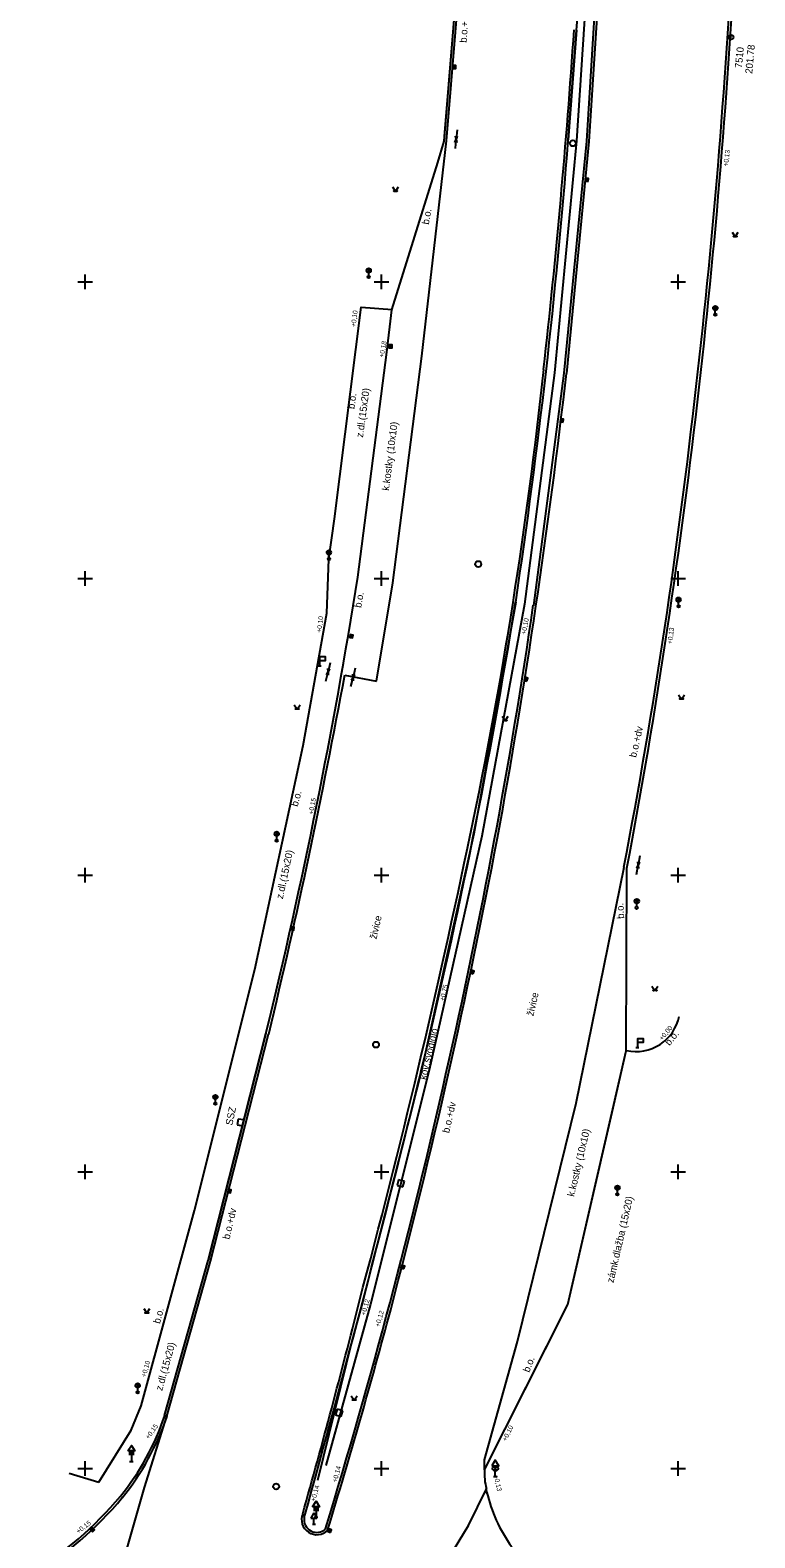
# Model space of a CAD drawing. Extents: x -599151 to -598424, y -1163476 to -1161924.
# Drawn here: x -598704.6 to -598643.5, y -1162630.9 to -1162503.8 of the extents above; entities that cross this region are included whole.
import ezdxf

# ---------------------------------------------------------------- set-up
doc = ezdxf.new("R2010")
doc.units = 0
for name, color, linetype in [('Vrstva 10', 7, 'Continuous'), ('Vrstva 14', 7, 'Continuous'), ('Vrstva 19', 7, 'Continuous'), ('Vrstva 2', 7, 'Continuous'), ('Vrstva 21', 7, 'Continuous'), ('Vrstva 23', 7, 'Continuous'), ('Vrstva 25', 7, 'Continuous'), ('Vrstva 29', 7, 'Continuous'), ('Vrstva 44', 7, 'Continuous'), ('Vrstva 49', 7, 'Continuous'), ('Vrstva 50', 7, 'Continuous'), ('Vrstva 62', 7, 'Continuous'), ('Vrstva 63', 7, 'Continuous'), ('Vrstva 7', 7, 'Continuous')]:
    doc.layers.add(name, color=color, linetype=linetype)

msp = doc.modelspace()

# ---------------------------------------------------------------- linework, layer by layer
at = {"layer": 'Vrstva 10'}
msp.add_lwpolyline([(-598657.82, -1162452.73), (-598658.26, -1162473.18), (-598658.32, -1162480.29), (-598658.04, -1162493.44), (-598657.77, -1162501.13), (-598658.57, -1162513.12), (-598660.43, -1162532.68), (-598662.96, -1162552.16), (-598666.55, -1162571.73), (-598670.98, -1162591.44), (-598675.92, -1162611.16), (-598679.71, -1162624.76)], dxfattribs=at)
at = {"layer": 'Vrstva 14'}
for points in [[(-598674.08, -1162517.01), (-598673.83, -1162517.38), (-598673.58, -1162517.01)], [(-598645.44, -1162520.83), (-598645.19, -1162521.2), (-598644.94, -1162520.83)], [(-598649.96, -1162559.8), (-598649.71, -1162560.18), (-598649.46, -1162559.8)], [(-598682.36, -1162560.65), (-598682.11, -1162561.02), (-598681.86, -1162560.65)], [(-598664.84, -1162561.62), (-598664.59, -1162561.99), (-598664.34, -1162561.62)], [(-598652.2, -1162584.37), (-598651.95, -1162584.74), (-598651.7, -1162584.37)], [(-598695.04, -1162611.54), (-598694.79, -1162611.92), (-598694.54, -1162611.54)], [(-598677.56, -1162618.88), (-598677.31, -1162619.25), (-598677.06, -1162618.88)]]:
    msp.add_lwpolyline(points, dxfattribs=at)
for centre in [(-598673.95, -1162517.36), (-598673.7, -1162517.36), (-598645.31, -1162521.18), (-598645.06, -1162521.18), (-598649.84, -1162560.15), (-598649.59, -1162560.15), (-598682.24, -1162561), (-598681.99, -1162561), (-598664.71, -1162561.97), (-598664.46, -1162561.97), (-598652.07, -1162584.72), (-598651.82, -1162584.72), (-598694.92, -1162611.89), (-598694.67, -1162611.89), (-598677.43, -1162619.23), (-598677.18, -1162619.23)]:
    msp.add_circle(centre, 0.025, dxfattribs=at)
at = {"layer": 'Vrstva 19'}
for p, q in [((-598680.35, -1162557.36), (-598680.1, -1162557.36)), ((-598680.23, -1162556.91), (-598680.23, -1162557.36)), ((-598653.55, -1162589.54), (-598653.3, -1162589.54)), ((-598653.42, -1162589.09), (-598653.42, -1162589.54)), ((-598680.71, -1162628.76), (-598680.96, -1162629.19)), ((-598680.71, -1162628.76), (-598680.46, -1162629.19)), ((-598680.96, -1162629.19), (-598680.46, -1162629.19)), ((-598680.83, -1162629.69), (-598680.58, -1162629.69)), ((-598680.71, -1162629.69), (-598680.71, -1162629.19))]:
    msp.add_line(p, q, dxfattribs=at)
for points in [[(-598680.23, -1162556.91), (-598679.73, -1162556.91), (-598679.73, -1162556.61), (-598680.23, -1162556.61)], [(-598653.42, -1162589.09), (-598652.92, -1162589.09), (-598652.92, -1162588.79), (-598653.42, -1162588.79)]]:
    msp.add_lwpolyline(points, close=True, dxfattribs=at)
at = {"layer": 'Vrstva 2'}
for radius in [0.187, 0.00896]:
    msp.add_circle((-598645.52, -1162504.39), radius, dxfattribs=at)
at = {"layer": 'Vrstva 21'}
for points in [[(-598658.56, -1162503.8), (-598659.26, -1162513.05)], [(-598663.69, -1162551.99), (-598667.22, -1162571.53), (-598671.67, -1162591.57), (-598676.61, -1162610.99), (-598677.51, -1162614.29), (-598680.39, -1162626.01)]]:
    msp.add_lwpolyline(points, dxfattribs=at)
for centre, radius, start, end in [((-598705.14, -1162500.39), 46.7, 355.8125, 2.7473), ((-599218.17, -1162469.19), 560.63, 351.5066, 355.5127)]:
    msp.add_arc(centre, radius, start, end, dxfattribs=at)
at = {"layer": 'Vrstva 23'}
for p, q in [((-598687.1, -1162595.56), (-598687.18, -1162596.05)), ((-598686.61, -1162595.64), (-598687.1, -1162595.56)), ((-598686.69, -1162596.13), (-598686.61, -1162595.64)), ((-598687.18, -1162596.05), (-598686.69, -1162596.13)), ((-598673.56, -1162600.67), (-598673.68, -1162601.15)), ((-598673.08, -1162600.79), (-598673.56, -1162600.67)), ((-598673.2, -1162601.27), (-598673.08, -1162600.79)), ((-598673.68, -1162601.15), (-598673.2, -1162601.27)), ((-598678.74, -1162620.01), (-598678.88, -1162620.49)), ((-598678.26, -1162620.15), (-598678.74, -1162620.01)), ((-598678.88, -1162620.49), (-598678.4, -1162620.63)), ((-598678.4, -1162620.63), (-598678.26, -1162620.15))]:
    msp.add_line(p, q, dxfattribs=at)
at = {"layer": 'Vrstva 25'}
for p, q in [((-598668.87, -1162506.78), (-598668.87, -1162507.03)), ((-598657.71, -1162516.53), (-598657.69, -1162516.29)), ((-598674.25, -1162530.31), (-598674.25, -1162530.56)), ((-598659.8, -1162536.81), (-598659.78, -1162536.57)), ((-598677.52, -1162554.76), (-598677.56, -1162555)), ((-598662.86, -1162558.61), (-598662.78, -1162558.37)), ((-598682.49, -1162579.38), (-598682.53, -1162579.62)), ((-598667.4, -1162583.29), (-598667.32, -1162583.05)), ((-598687.81, -1162601.52), (-598687.85, -1162601.76)), ((-598673.25, -1162608.15), (-598673.17, -1162607.91)), ((-598699.46, -1162630.26), (-598699.28, -1162630.1)), ((-598679.42, -1162630.37), (-598679.34, -1162630.13))]:
    msp.add_line(p, q, dxfattribs=at)
for points in [[(-598668.99, -1162506.78), (-598668.99, -1162507.03), (-598668.74, -1162507.03), (-598668.74, -1162506.78)], [(-598657.59, -1162516.55), (-598657.56, -1162516.3), (-598657.81, -1162516.27), (-598657.84, -1162516.52)], [(-598674.38, -1162530.31), (-598674.38, -1162530.56), (-598674.12, -1162530.56), (-598674.12, -1162530.31)], [(-598659.68, -1162536.83), (-598659.65, -1162536.58), (-598659.9, -1162536.55), (-598659.93, -1162536.8)], [(-598677.64, -1162554.74), (-598677.68, -1162554.98), (-598677.44, -1162555.02), (-598677.4, -1162554.78)], [(-598662.74, -1162558.65), (-598662.66, -1162558.41), (-598662.9, -1162558.33), (-598662.98, -1162558.57)], [(-598682.61, -1162579.36), (-598682.65, -1162579.6), (-598682.41, -1162579.64), (-598682.37, -1162579.4)], [(-598667.28, -1162583.33), (-598667.2, -1162583.09), (-598667.44, -1162583.01), (-598667.52, -1162583.25)], [(-598687.93, -1162601.5), (-598687.97, -1162601.74), (-598687.73, -1162601.78), (-598687.69, -1162601.54)], [(-598673.13, -1162608.19), (-598673.05, -1162607.95), (-598673.29, -1162607.87), (-598673.37, -1162608.11)], [(-598699.38, -1162630.36), (-598699.19, -1162630.19), (-598699.36, -1162630), (-598699.55, -1162630.17)], [(-598679.3, -1162630.41), (-598679.22, -1162630.17), (-598679.46, -1162630.09), (-598679.54, -1162630.33)]]:
    msp.add_lwpolyline(points, close=True, dxfattribs=at)
for centre in [(-598658.87, -1162513.33), (-598666.85, -1162548.79), (-598675.47, -1162589.29), (-598683.89, -1162626.52)]:
    msp.add_circle(centre, 0.25, dxfattribs=at)
at = {"layer": 'Vrstva 29'}
for p, q in [((-598675.94, -1162524.18), (-598676.21, -1162523.91)), ((-598676.21, -1162524.18), (-598675.95, -1162523.92)), ((-598676.08, -1162524.51), (-598676.08, -1162524.24)), ((-598646.99, -1162527.35), (-598646.73, -1162527.08)), ((-598646.72, -1162527.35), (-598646.99, -1162527.08)), ((-598646.86, -1162527.68), (-598646.86, -1162527.41)), ((-598679.3, -1162547.94), (-598679.57, -1162547.67)), ((-598679.57, -1162547.94), (-598679.31, -1162547.68)), ((-598679.44, -1162548.27), (-598679.44, -1162548)), ((-598649.82, -1162551.92), (-598650.09, -1162551.65)), ((-598650.09, -1162551.92), (-598649.83, -1162551.66)), ((-598649.96, -1162552.25), (-598649.96, -1162551.98)), ((-598683.7, -1162571.66), (-598683.97, -1162571.39)), ((-598683.97, -1162571.66), (-598683.71, -1162571.4)), ((-598683.84, -1162571.99), (-598683.84, -1162571.72)), ((-598653.61, -1162577.33), (-598653.35, -1162577.06)), ((-598653.34, -1162577.33), (-598653.61, -1162577.06)), ((-598653.48, -1162577.66), (-598653.48, -1162577.39)), ((-598689.14, -1162593.84), (-598688.88, -1162593.57)), ((-598688.87, -1162593.84), (-598689.14, -1162593.57)), ((-598689.01, -1162594.17), (-598689.01, -1162593.9)), ((-598654.97, -1162601.48), (-598655.24, -1162601.21)), ((-598655.24, -1162601.48), (-598654.98, -1162601.22)), ((-598655.11, -1162601.81), (-598655.11, -1162601.54)), ((-598695.42, -1162618.15), (-598695.69, -1162617.88)), ((-598695.69, -1162618.15), (-598695.43, -1162617.89)), ((-598695.56, -1162618.48), (-598695.56, -1162618.21))]:
    msp.add_line(p, q, dxfattribs=at)
for centre, radius in [((-598676.08, -1162524.05), 0.188), ((-598676.08, -1162524.61), 0.1), ((-598646.86, -1162527.22), 0.188), ((-598646.86, -1162527.78), 0.1), ((-598679.44, -1162547.81), 0.188), ((-598679.44, -1162548.37), 0.1), ((-598649.96, -1162551.79), 0.188), ((-598649.96, -1162552.35), 0.1), ((-598683.84, -1162571.53), 0.188), ((-598683.84, -1162572.09), 0.1), ((-598653.48, -1162577.2), 0.188), ((-598653.48, -1162577.76), 0.1), ((-598689.01, -1162593.71), 0.188), ((-598689.01, -1162594.27), 0.1), ((-598655.11, -1162601.35), 0.188), ((-598655.11, -1162601.91), 0.1), ((-598695.56, -1162618.02), 0.188), ((-598695.56, -1162618.58), 0.1)]:
    msp.add_circle(centre, radius, dxfattribs=at)
at = {"layer": 'Vrstva 44'}
for p, q in [((-598696.31, -1162623.66), (-598695.86, -1162623.66)), ((-598696.31, -1162623.81), (-598695.87, -1162623.81)), ((-598696.09, -1162623.51), (-598696.09, -1162624.41)), ((-598696.24, -1162624.41), (-598695.94, -1162624.41)), ((-598665.26, -1162624.83), (-598665.56, -1162625.18)), ((-598665.56, -1162624.83), (-598665.26, -1162625.18)), ((-598665.56, -1162625.68), (-598665.26, -1162625.68)), ((-598665.41, -1162625.68), (-598665.41, -1162625.23)), ((-598680.74, -1162628.37), (-598680.29, -1162628.37)), ((-598680.74, -1162628.52), (-598680.3, -1162628.52)), ((-598680.52, -1162628.22), (-598680.52, -1162629.12)), ((-598680.67, -1162629.12), (-598680.37, -1162629.12))]:
    msp.add_line(p, q, dxfattribs=at)
for points in [[(-598696.39, -1162623.52), (-598696.09, -1162623.06), (-598695.79, -1162623.52)], [(-598680.82, -1162628.23), (-598680.52, -1162627.77), (-598680.22, -1162628.23)]]:
    msp.add_lwpolyline(points, close=True, dxfattribs=at)
msp.add_lwpolyline([(-598665.71, -1162624.78), (-598665.11, -1162624.78), (-598665.41, -1162624.32), (-598665.71, -1162624.78)], dxfattribs=at)
msp.add_circle((-598665.41, -1162625), 0.228, dxfattribs=at)
at = {"layer": 'Vrstva 49'}
for p, q in [((-598668.81, -1162513.25), (-598668.71, -1162512.99)), ((-598668.78, -1162513.78), (-598668.71, -1162512.99)), ((-598668.71, -1162512.99), (-598668.76, -1162512.72)), ((-598668.64, -1162512.2), (-598668.71, -1162512.99)), ((-598668.62, -1162512.73), (-598668.71, -1162512.99)), ((-598668.71, -1162512.99), (-598668.66, -1162513.27)), ((-598679.51, -1162557.88), (-598679.52, -1162557.6)), ((-598679.33, -1162557.1), (-598679.51, -1162557.88)), ((-598679.38, -1162557.63), (-598679.51, -1162557.88)), ((-598677.22, -1162557.57), (-598677.4, -1162558.34)), ((-598679.69, -1162558.65), (-598679.51, -1162557.88)), ((-598679.64, -1162558.12), (-598679.51, -1162557.88)), ((-598679.51, -1162557.88), (-598679.5, -1162558.15)), ((-598677.58, -1162559.11), (-598677.4, -1162558.34)), ((-598677.53, -1162558.58), (-598677.4, -1162558.34)), ((-598677.4, -1162558.34), (-598677.41, -1162558.06)), ((-598677.27, -1162558.09), (-598677.4, -1162558.34)), ((-598677.4, -1162558.34), (-598677.39, -1162558.62)), ((-598653.51, -1162574.94), (-598653.37, -1162574.17)), ((-598653.51, -1162574.94), (-598653.37, -1162574.17)), ((-598653.49, -1162574.42), (-598653.37, -1162574.17)), ((-598653.49, -1162574.42), (-598653.37, -1162574.17)), ((-598653.37, -1162574.17), (-598653.39, -1162573.89)), ((-598653.37, -1162574.17), (-598653.39, -1162573.89)), ((-598653.23, -1162573.39), (-598653.37, -1162574.17)), ((-598653.23, -1162573.39), (-598653.37, -1162574.17)), ((-598653.25, -1162573.91), (-598653.37, -1162574.17)), ((-598653.25, -1162573.91), (-598653.37, -1162574.17)), ((-598653.37, -1162574.17), (-598653.35, -1162574.44)), ((-598653.37, -1162574.17), (-598653.35, -1162574.44))]:
    msp.add_line(p, q, dxfattribs=at)
at = {"layer": 'Vrstva 62'}
for p, q in [((-598700, -1162525.62), (-598700, -1162524.38)), ((-598675, -1162525.62), (-598675, -1162524.38)), ((-598650, -1162525.62), (-598650, -1162524.38)), ((-598700.62, -1162525), (-598699.38, -1162525)), ((-598675.62, -1162525), (-598674.38, -1162525)), ((-598650.62, -1162525), (-598649.38, -1162525)), ((-598700.62, -1162550), (-598699.38, -1162550)), ((-598700, -1162550.62), (-598700, -1162549.38)), ((-598675.62, -1162550), (-598674.38, -1162550)), ((-598675, -1162550.62), (-598675, -1162549.38)), ((-598650.62, -1162550), (-598649.38, -1162550)), ((-598650, -1162550.62), (-598650, -1162549.38)), ((-598700.62, -1162575), (-598699.38, -1162575)), ((-598700, -1162575.62), (-598700, -1162574.38)), ((-598675.62, -1162575), (-598674.38, -1162575)), ((-598675, -1162575.62), (-598675, -1162574.38)), ((-598650.62, -1162575), (-598649.38, -1162575)), ((-598650, -1162575.62), (-598650, -1162574.38)), ((-598700, -1162600.62), (-598700, -1162599.38)), ((-598675, -1162600.62), (-598675, -1162599.38)), ((-598650, -1162600.62), (-598650, -1162599.38)), ((-598700.62, -1162600), (-598699.38, -1162600)), ((-598675.62, -1162600), (-598674.38, -1162600)), ((-598650.62, -1162600), (-598649.38, -1162600)), ((-598700.62, -1162625), (-598699.38, -1162625)), ((-598700, -1162625.62), (-598700, -1162624.38)), ((-598675.62, -1162625), (-598674.38, -1162625)), ((-598675, -1162625.62), (-598675, -1162624.38)), ((-598650.62, -1162625), (-598649.38, -1162625)), ((-598650, -1162625.62), (-598650, -1162624.38))]:
    msp.add_line(p, q, dxfattribs=at)
at = {"layer": 'Vrstva 63'}
for points in [[(-598655.01, -1162433.67), (-598655.31, -1162452.9), (-598655.81, -1162473.2), (-598656.5, -1162493.58), (-598657.72, -1162513.16), (-598659.63, -1162532.7), (-598662.2, -1162552.27)], [(-598677, -1162549.89), (-598674.55, -1162530.94), (-598674.13, -1162527.37), (-598670.27, -1162514.94), (-598669.73, -1162513.14), (-598668.58, -1162499.17), (-598671.29, -1162474.14), (-598671.26, -1162472.7), (-598671, -1162451.83)], [(-598659.26, -1162513.05), (-598658.56, -1162503.8)], [(-598666.32, -1162625.11), (-598659.31, -1162611.19), (-598654.37, -1162589.8), (-598654.31, -1162574.43)], [(-598693.29, -1162620.54), (-598689.63, -1162607.49), (-598684.75, -1162588.35)], [(-598700.37, -1162646.94), (-598697.95, -1162636.94), (-598695, -1162626.61), (-598693.1, -1162620.6), (-598693.29, -1162620.54)], [(-598669.32, -1162632.55), (-598667.68, -1162629.8), (-598666.16, -1162626.73)]]:
    msp.add_lwpolyline(points, dxfattribs=at)
for centre, radius, start, end in [((-599239.98, -1162466.52), 595.58, 353.50561, 357.33967), ((-599218.17, -1162469.19), 560.63, 351.5066, 355.5127), ((-599199.46, -1162471.82), 554.72, 349.3408, 353.577), ((-599157.77, -1162473.02), 486.88, 346.2979, 350.9161), ((-599164.87, -1162471.54), 507.59, 346.3216, 350.8804), ((-599159.28, -1162479.93), 502.31, 347.1369, 351.7202), ((-599880.11, -1162294.51), 1244.42, 344.40041, 346.18929), ((-599185.91, -1162475.53), 529.26, 343.0208, 347.3145), ((-598661.72, -1162625.47), 4.61, 175.4734, 195.8077), ((-598680.46, -1162629.31), 1.08, 171.5488, 313.4572)]:
    msp.add_arc(centre, radius, start, end, dxfattribs=at)
at = {"layer": 'Vrstva 7'}
for points in [[(-598677, -1162549.89), (-598674.55, -1162530.94), (-598674.13, -1162527.37), (-598670.27, -1162514.94), (-598669.73, -1162513.14), (-598669.69, -1162512.75), (-598668.58, -1162499.17), (-598669.39, -1162491.62), (-598671.29, -1162474.14), (-598671.26, -1162472.7), (-598671, -1162451.83)], [(-598655.31, -1162452.9), (-598655.81, -1162473.2), (-598656.5, -1162493.58), (-598657.72, -1162513.16), (-598659.63, -1162532.7), (-598662.2, -1162552.27)], [(-598655.09, -1162452.9), (-598655.58, -1162473.23), (-598656.26, -1162493.58), (-598657.52, -1162513.17), (-598659.42, -1162532.73)], [(-598669.52, -1162513.11), (-598668.38, -1162499.19)], [(-598659.26, -1162513.05), (-598658.56, -1162503.8)], [(-598675.42, -1162558.65), (-598674.06, -1162550.37), (-598671.6, -1162531.27), (-598669.52, -1162513.11)], [(-598679.62, -1162552.92), (-598679.44, -1162548.37), (-598678.96, -1162544.97), (-598676.71, -1162527.14), (-598674.11, -1162527.35)], [(-598698.84, -1162626.17), (-598696.12, -1162621.79), (-598695.27, -1162619.74), (-598690.77, -1162603.28), (-598685.69, -1162582.95), (-598681.62, -1162564.08), (-598679.62, -1162552.92)], [(-598678.11, -1162558.14), (-598675.42, -1162558.65)], [(-598658.59, -1162594.23), (-598654.56, -1162574.34)], [(-598654.37, -1162589.8), (-598654.31, -1162574.43)], [(-598693.1, -1162620.6), (-598689.42, -1162607.53), (-598684.52, -1162588.4)], [(-598684.75, -1162588.35), (-598689.63, -1162607.49)], [(-598666.32, -1162625.11), (-598661.22, -1162614.98), (-598659.31, -1162611.19), (-598655.56, -1162594.97), (-598654.37, -1162589.8)], [(-598666.32, -1162625.11), (-598666.33, -1162624.29), (-598663.54, -1162614.3), (-598658.59, -1162594.23)], [(-598693.29, -1162620.54), (-598689.63, -1162607.49)], [(-598701.34, -1162625.4), (-598698.84, -1162626.17)]]:
    msp.add_lwpolyline(points, dxfattribs=at)
for centre, radius, start, end in [((-599244.4, -1162465.66), 599.82, 353.47468, 357.27997), ((-599239.98, -1162466.52), 595.58, 353.50561, 357.33967), ((-599333.06, -1162457.65), 675.87, 353.65117, 356.08639), ((-599218.17, -1162469.19), 560.63, 351.5066, 355.5127), ((-599051.18, -1162490.95), 392.05, 348.142, 353.9323), ((-599231.88, -1162467.75), 576.14, 349.58868, 353.52449), ((-599166.94, -1162476.61), 521.61, 349.2016, 353.7036), ((-599199.46, -1162471.82), 554.72, 349.3408, 353.577), ((-599157.77, -1162473.02), 486.88, 346.2979, 350.9161), ((-599164.87, -1162471.54), 507.59, 346.3216, 350.8804), ((-599159.28, -1162479.93), 502.31, 347.1369, 351.7202), ((-599244.25, -1162454.02), 575.64, 346.50023, 349.57935), ((-599349.18, -1162430.23), 696.16, 344.95104, 348.29144), ((-599239.41, -1162462.84), 584.44, 345.24955, 349.2478), ((-598653.54, -1162586.17), 3.7, 257.5359, 348.4572), ((-599880.11, -1162294.51), 1244.42, 344.40041, 346.18928), ((-599185.91, -1162475.53), 529.26, 343.0208, 347.3145), ((-599264.9, -1162463.64), 606.19, 344.1872, 345.93197), ((-599229.73, -1162462.62), 575.14, 343.05959, 344.98275), ((-598714.42, -1162613.36), 22.33, 321.2186, 341.2315), ((-598714.42, -1162613.36), 22.53, 321.2136, 341.2315), ((-598661.72, -1162625.47), 4.61, 175.4734, 195.8077), ((-598720.87, -1162607.4), 31.09, 301.4995, 320.1111), ((-598720.87, -1162607.4), 31.29, 301.4995, 320.1146), ((-598675.35, -1162628.45), 9.34, 7.9103, 10.5819), ((-598654.05, -1162624.25), 12.38, 192.9301, 204.3765), ((-598680.46, -1162629.31), 1.28, 157.8472, 315.9128), ((-598680.46, -1162629.31), 1.08, 171.5488, 313.4576), ((-598653.56, -1162624.03), 12.92, 204.3767, 215.9354)]:
    msp.add_arc(centre, radius, start, end, dxfattribs=at)

# ---------------------------------------------------------------- texts
at = {"layer": 'Vrstva 2'}
for s, rotation, p in [('7510', 84.5632, (-598644.62, -1162507.02)), ('201.78', 84.7088, (-598643.75, -1162507.49))]:
    msp.add_text(s, height=0.6, rotation=rotation, dxfattribs=at).set_placement(p)
at = {"layer": 'Vrstva 49'}
for s, rotation, p in [('b.o.+dv', 86.1447, (-598667.83, -1162504.87)), ('b.o.', 79.7597, (-598671.02, -1162520.21)), ('b.o.', 82.631, (-598677.29, -1162535.75)), ('z.dl.(15x20)', 82.2147, (-598676.57, -1162538.15)), ('k.kostky (10x10)', 82.6755, (-598674.38, -1162542.63)), ('b.o.', 79.7597, (-598676.72, -1162552.51)), ('b.o.+dv', 77.1507, (-598653.54, -1162565.13)), ('b.o.', 74.7101, (-598682.08, -1162569.27)), ('z.dl.(15x20)', 77.9005, (-598683.33, -1162577.05)), ('b.o.', 93.258, (-598654.54, -1162578.67)), ('živice', 77.0378, (-598675.43, -1162580.44)), ('živice', 77.0378, (-598662.2, -1162586.91)), ('kov.svodidlo', 76.659, (-598671.25, -1162592.29)), ('b.o.', 50.4895, (-598650.73, -1162589.42)), ('SSZ', 78.206, (-598687.58, -1162596.13)), ('b.o.+dv', 77.1507, (-598669.31, -1162596.78)), ('k.kostky (10x10)', 76.6772, (-598658.77, -1162602.14)), ('zámk.dlažba (15x20)', 77.1141, (-598655.45, -1162609.4)), ('b.o.+dv', 77.1507, (-598687.82, -1162605.74)), ('b.o.', 74.7101, (-598693.69, -1162612.85)), ('z.dl.(15x20)', 74.4453, (-598693.5, -1162618.5)), ('b.o.', 69.0295, (-598662.55, -1162616.96))]:
    msp.add_text(s, height=0.6, rotation=rotation, dxfattribs=at).set_placement(p)
at = {"layer": 'Vrstva 50'}
for s, rotation, p in [('+0,13', 82.9329, (-598645.8, -1162515.3)), ('+0,10', 82.7971, (-598677.19, -1162528.82)), ('+0,18', 79.7597, (-598674.82, -1162531.41)), ('+0,10', 82.7971, (-598680.09, -1162554.59)), ('+0,10', 79.7597, (-598662.83, -1162554.76)), ('+0,13', 82.9329, (-598650.51, -1162555.55)), ('+0,15', 79.7597, (-598680.77, -1162569.91)), ('+0.75', 76.8402, (-598669.72, -1162585.64)), ('+0,00', 50.4895, (-598651.33, -1162588.97)), ('+0,12', 74.4281, (-598676.37, -1162612.14)), ('+0,12', 74.4281, (-598675.17, -1162613.11)), ('+0,10', 74.7101, (-598694.88, -1162617.34)), ('+0,15', 54.7315, (-598694.62, -1162622.58)), ('+0,10', 63.8119, (-598664.49, -1162622.75)), ('+0,14', 74.8603, (-598678.78, -1162626.21)), ('+0,13', 282.7268, (-598665.55, -1162625.6)), ('+0,14', 74.8603, (-598680.6, -1162627.83)), ('+0,15', 37.3779, (-598700.56, -1162630.53))]:
    msp.add_text(s, height=0.4, rotation=rotation, dxfattribs=at).set_placement(p)

doc.saveas('drawing.dxf')
